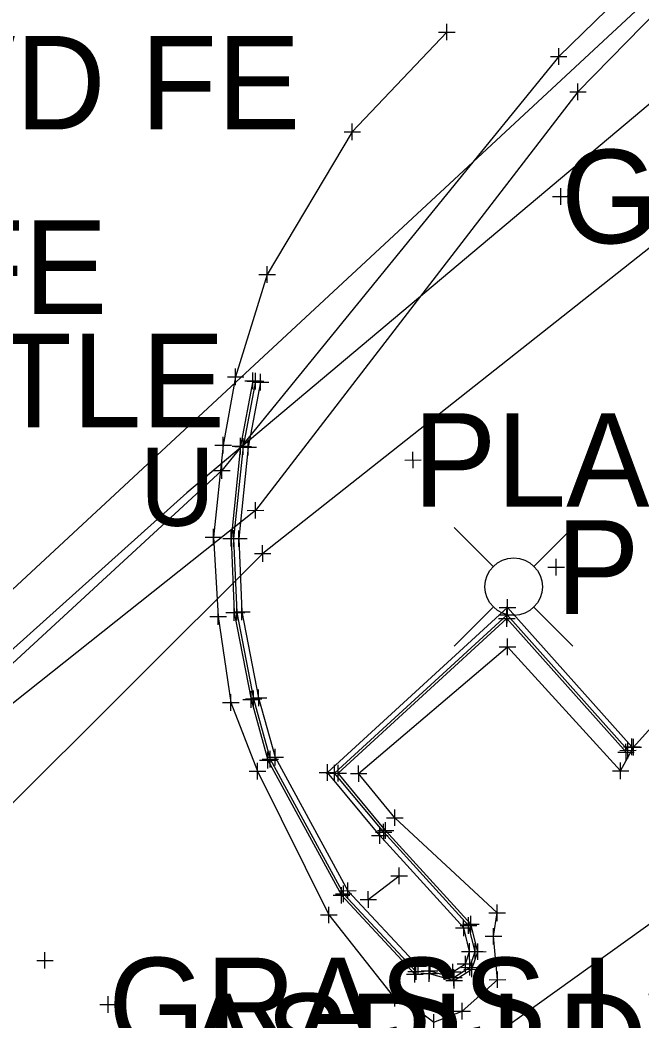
# Model space of a CAD drawing. Extents: x -1 to 1157254, y -1 to 2021979.
# Drawn here: x 1147532.2 to 1147580, y 2017383.4 to 2017460.4 of the extents above; entities that cross this region are included whole.
import ezdxf

# ---------------------------------------------------------------- set-up
doc = ezdxf.new("R2010")
doc.units = 0
for name, color, linetype in [('S_BUILDING_ANNOT', 7, 'Continuous'), ('S_CAL_CORNER_ANNOT', 7, 'Continuous'), ('S_CATCH_BASIN', 7, 'Continuous'), ('S_CONTOUR_MAJOR', 7, 'Continuous'), ('S_CTL_TABLE', 7, 'Continuous'), ('S_DRIVEWAY_ANNOT', 7, 'Continuous'), ('S_DROP_INLET', 7, 'Continuous'), ('S_DTM_PAVEMENT', 7, 'Continuous'), ('S_EDGE_BITUMINOUS_ANNOT', 7, 'Continuous'), ('S_EDGE_PAVEMENT', 7, 'Continuous'), ('S_EDGE_PAVEMENT_ANNOT', 7, 'Continuous'), ('S_ENV_CONSTRAINT', 7, 'Continuous'), ('S_FENCE', 7, 'Continuous'), ('S_GATE', 7, 'Continuous'), ('S_GATE_ANNOT', 7, 'Continuous')]:
    doc.layers.add(name, color=color, linetype=linetype)

msp = doc.modelspace()

# ---------------------------------------------------------------- linework, layer by layer
at = {"layer": 'S_BUILDING_ANNOT'}
for p, q in [((1147565.012, 2017458.822), (1147565.009, 2017460.094)), ((1147564.374, 2017459.456), (1147565.647, 2017459.459)), ((1147565.011, 2017459.458), (1147565.011, 2017459.458)), ((1147573.624, 2017456.932), (1147573.622, 2017458.204)), ((1147572.987, 2017457.566), (1147574.259, 2017457.569)), ((1147573.623, 2017457.568), (1147573.623, 2017457.568)), ((1147575.105, 2017454.225), (1147575.103, 2017455.498)), ((1147574.468, 2017454.86), (1147575.74, 2017454.863)), ((1147575.104, 2017454.862), (1147575.104, 2017454.862)), ((1147557.746, 2017451.147), (1147557.743, 2017452.42)), ((1147557.108, 2017451.782), (1147558.381, 2017451.785)), ((1147557.744, 2017451.783), (1147557.744, 2017451.783)), ((1147573.787, 2017446.169), (1147573.785, 2017447.442)), ((1147573.15, 2017446.804), (1147574.422, 2017446.807)), ((1147573.786, 2017446.805), (1147573.786, 2017446.805)), ((1147551.193, 2017440.159), (1147551.191, 2017441.431)), ((1147550.556, 2017440.794), (1147551.828, 2017440.796)), ((1147551.192, 2017440.795), (1147551.192, 2017440.795)), ((1147548.774, 2017432.29), (1147548.772, 2017433.562)), ((1147548.137, 2017432.924), (1147549.409, 2017432.927)), ((1147548.773, 2017432.926), (1147548.773, 2017432.926)), ((1147549.663, 2017432.585), (1147550.935, 2017432.588)), ((1147550.3, 2017431.951), (1147550.298, 2017433.223)), ((1147550.299, 2017432.587), (1147550.299, 2017432.587)), ((1147550.693, 2017431.877), (1147550.691, 2017433.149)), ((1147550.056, 2017432.511), (1147551.328, 2017432.514)), ((1147550.692, 2017432.513), (1147550.692, 2017432.513)), ((1147547.814, 2017427.03), (1147547.812, 2017428.303)), ((1147549.351, 2017426.933), (1147549.349, 2017428.206)), ((1147549.747, 2017426.875), (1147549.745, 2017428.148)), ((1147547.177, 2017427.665), (1147548.449, 2017427.668)), ((1147547.813, 2017427.667), (1147547.813, 2017427.667)), ((1147548.714, 2017427.568), (1147549.986, 2017427.571)), ((1147549.11, 2017427.51), (1147550.382, 2017427.513)), ((1147549.35, 2017427.57), (1147549.35, 2017427.57)), ((1147549.746, 2017427.512), (1147549.746, 2017427.512)), ((1147561.779, 2017426.526), (1147563.052, 2017426.529)), ((1147562.417, 2017425.891), (1147562.414, 2017427.164)), ((1147562.415, 2017426.528), (1147562.415, 2017426.528)), ((1147547.075, 2017425.716), (1147548.347, 2017425.719)), ((1147547.712, 2017425.081), (1147547.71, 2017426.354)), ((1147547.711, 2017425.718), (1147547.711, 2017425.718)), ((1147549.66, 2017422.652), (1147550.932, 2017422.655)), ((1147550.297, 2017422.017), (1147550.295, 2017423.29)), ((1147550.296, 2017422.653), (1147550.296, 2017422.653)), ((1147547.077, 2017419.959), (1147547.075, 2017421.232)), ((1147548.621, 2017419.854), (1147548.619, 2017421.127)), ((1147549.022, 2017419.842), (1147549.02, 2017421.115)), ((1147546.44, 2017420.594), (1147547.712, 2017420.597)), ((1147547.076, 2017420.595), (1147547.076, 2017420.595)), ((1147547.984, 2017420.489), (1147549.256, 2017420.492)), ((1147548.385, 2017420.477), (1147549.657, 2017420.48)), ((1147548.62, 2017420.49), (1147548.62, 2017420.49)), ((1147549.021, 2017420.478), (1147549.021, 2017420.478)), ((1147550.852, 2017418.691), (1147550.85, 2017419.964)), ((1147550.215, 2017419.326), (1147551.487, 2017419.329)), ((1147550.851, 2017419.327), (1147550.851, 2017419.327)), ((1147573.419, 2017417.651), (1147573.417, 2017418.924)), ((1147572.782, 2017418.286), (1147574.054, 2017418.289)), ((1147573.418, 2017418.287), (1147573.418, 2017418.287)), ((1147569.678, 2017414.552), (1147569.675, 2017415.824)), ((1147547.437, 2017413.844), (1147547.435, 2017415.116)), ((1147548.857, 2017414.169), (1147548.855, 2017415.441)), ((1147549.255, 2017414.216), (1147549.253, 2017415.488)), ((1147569.041, 2017415.187), (1147570.313, 2017415.19)), ((1147569.649, 2017413.983), (1147569.646, 2017415.255)), ((1147569.677, 2017415.188), (1147569.677, 2017415.188)), ((1147546.8, 2017414.479), (1147548.072, 2017414.481)), ((1147547.436, 2017414.48), (1147547.436, 2017414.48)), ((1147548.22, 2017414.804), (1147549.492, 2017414.806)), ((1147548.618, 2017414.851), (1147549.89, 2017414.853)), ((1147548.856, 2017414.805), (1147548.856, 2017414.805)), ((1147549.254, 2017414.852), (1147549.254, 2017414.852)), ((1147569.012, 2017414.618), (1147570.284, 2017414.62)), ((1147569.648, 2017414.619), (1147569.648, 2017414.619)), ((1147569.685, 2017411.513), (1147569.682, 2017412.785)), ((1147569.048, 2017412.148), (1147570.32, 2017412.15)), ((1147569.684, 2017412.149), (1147569.684, 2017412.149)), ((1147550.155, 2017407.507), (1147550.153, 2017408.779)), ((1147550.544, 2017407.599), (1147550.542, 2017408.871)), ((1147548.398, 2017407.233), (1147548.396, 2017408.505)), ((1147549.518, 2017408.142), (1147550.79, 2017408.144)), ((1147549.907, 2017408.234), (1147551.179, 2017408.236)), ((1147550.154, 2017408.143), (1147550.154, 2017408.143)), ((1147550.543, 2017408.235), (1147550.543, 2017408.235)), ((1147547.761, 2017407.868), (1147549.033, 2017407.87)), ((1147548.397, 2017407.869), (1147548.397, 2017407.869)), ((1147579.247, 2017403.819), (1147579.245, 2017405.091)), ((1147579.367, 2017403.799), (1147579.365, 2017405.071)), ((1147551.437, 2017402.869), (1147551.435, 2017404.142)), ((1147551.811, 2017403.02), (1147551.809, 2017404.293)), ((1147578.311, 2017404.187), (1147579.583, 2017404.19)), ((1147578.61, 2017404.453), (1147579.882, 2017404.456)), ((1147578.73, 2017404.433), (1147580.002, 2017404.436)), ((1147578.948, 2017403.552), (1147578.946, 2017404.825)), ((1147578.947, 2017404.189), (1147578.947, 2017404.189)), ((1147579.246, 2017404.455), (1147579.246, 2017404.455)), ((1147579.366, 2017404.435), (1147579.366, 2017404.435)), ((1147550.8, 2017403.504), (1147552.072, 2017403.507)), ((1147551.174, 2017403.655), (1147552.446, 2017403.658)), ((1147551.436, 2017403.506), (1147551.436, 2017403.506)), ((1147551.81, 2017403.657), (1147551.81, 2017403.657)), ((1147549.813, 2017402.583), (1147551.085, 2017402.586)), ((1147550.45, 2017401.948), (1147550.448, 2017403.221)), ((1147550.449, 2017402.585), (1147550.449, 2017402.585)), ((1147555.83, 2017401.844), (1147555.827, 2017403.117)), ((1147556.381, 2017401.806), (1147556.378, 2017403.079)), ((1147558.235, 2017401.758), (1147558.232, 2017403.031)), ((1147577.747, 2017402.609), (1147579.019, 2017402.612)), ((1147578.384, 2017401.974), (1147578.382, 2017403.247)), ((1147578.383, 2017402.611), (1147578.383, 2017402.611)), ((1147555.192, 2017402.479), (1147556.465, 2017402.482)), ((1147555.743, 2017402.441), (1147557.016, 2017402.444)), ((1147555.828, 2017402.481), (1147555.828, 2017402.481)), ((1147556.379, 2017402.443), (1147556.379, 2017402.443)), ((1147557.597, 2017402.393), (1147558.87, 2017402.396)), ((1147558.233, 2017402.395), (1147558.233, 2017402.395)), ((1147561.011, 2017398.366), (1147561.008, 2017399.639)), ((1147560.373, 2017399.001), (1147561.646, 2017399.004)), ((1147561.009, 2017399.002), (1147561.009, 2017399.002)), ((1147559.858, 2017396.987), (1147559.855, 2017398.26)), ((1147560.16, 2017397.25), (1147560.157, 2017398.523)), ((1147559.22, 2017397.622), (1147560.493, 2017397.625)), ((1147559.522, 2017397.885), (1147560.795, 2017397.888)), ((1147559.856, 2017397.623), (1147559.856, 2017397.623)), ((1147560.158, 2017397.886), (1147560.158, 2017397.886)), ((1147561.355, 2017393.89), (1147561.352, 2017395.163)), ((1147560.717, 2017394.525), (1147561.99, 2017394.528)), ((1147561.353, 2017394.526), (1147561.353, 2017394.526)), ((1147556.768, 2017393.387), (1147558.041, 2017393.39)), ((1147557.079, 2017392.516), (1147557.076, 2017393.789)), ((1147557.406, 2017392.752), (1147557.403, 2017394.025)), ((1147557.404, 2017393.388), (1147557.404, 2017393.388)), ((1147558.979, 2017392.081), (1147558.976, 2017393.354)), ((1147556.441, 2017393.151), (1147557.714, 2017393.154)), ((1147557.077, 2017393.152), (1147557.077, 2017393.152)), ((1147558.341, 2017392.716), (1147559.614, 2017392.719)), ((1147558.977, 2017392.717), (1147558.977, 2017392.717)), ((1147555.934, 2017390.884), (1147555.931, 2017392.157)), ((1147568.887, 2017391.043), (1147568.884, 2017392.316)), ((1147555.296, 2017391.519), (1147556.569, 2017391.522)), ((1147555.932, 2017391.52), (1147555.932, 2017391.52)), ((1147566.313, 2017389.886), (1147566.31, 2017391.158)), ((1147566.676, 2017390.081), (1147566.673, 2017391.353)), ((1147568.249, 2017391.678), (1147569.522, 2017391.681)), ((1147568.886, 2017391.679), (1147568.886, 2017391.679)), ((1147565.675, 2017390.521), (1147566.948, 2017390.524)), ((1147566.038, 2017390.716), (1147567.311, 2017390.719)), ((1147566.312, 2017390.522), (1147566.312, 2017390.522)), ((1147566.675, 2017390.717), (1147566.675, 2017390.717)), ((1147568.612, 2017389.244), (1147568.609, 2017390.516)), ((1147567.974, 2017389.879), (1147569.247, 2017389.882)), ((1147568.611, 2017389.88), (1147568.611, 2017389.88)), ((1147566.132, 2017388.716), (1147567.405, 2017388.719)), ((1147566.549, 2017388.701), (1147567.822, 2017388.704)), ((1147566.77, 2017388.081), (1147566.767, 2017389.353)), ((1147566.769, 2017388.717), (1147566.769, 2017388.717)), ((1147567.187, 2017388.066), (1147567.184, 2017389.338)), ((1147567.186, 2017388.702), (1147567.186, 2017388.702)), ((1147533.47, 2017388.027), (1147534.743, 2017388.029)), ((1147534.108, 2017387.392), (1147534.105, 2017388.664)), ((1147534.106, 2017388.028), (1147534.106, 2017388.028)), ((1147562.812, 2017386.947), (1147562.809, 2017388.219)), ((1147563.732, 2017386.988), (1147563.729, 2017388.26)), ((1147566.448, 2017387.115), (1147566.445, 2017388.387)), ((1147566.783, 2017386.855), (1147566.78, 2017388.127)), ((1147562.007, 2017387.175), (1147563.28, 2017387.177)), ((1147562.174, 2017387.582), (1147563.447, 2017387.584)), ((1147562.645, 2017386.54), (1147562.642, 2017387.812)), ((1147562.644, 2017387.176), (1147562.644, 2017387.176)), ((1147562.81, 2017387.583), (1147562.81, 2017387.583)), ((1147563.048, 2017387.221), (1147564.321, 2017387.223)), ((1147563.094, 2017387.623), (1147564.367, 2017387.625)), ((1147563.686, 2017386.586), (1147563.683, 2017387.858)), ((1147563.684, 2017387.222), (1147563.684, 2017387.222)), ((1147563.73, 2017387.624), (1147563.73, 2017387.624)), ((1147565.491, 2017386.5), (1147565.488, 2017387.772)), ((1147565.557, 2017386.067), (1147565.554, 2017387.339)), ((1147565.81, 2017387.75), (1147567.083, 2017387.752)), ((1147566.145, 2017387.49), (1147567.418, 2017387.492)), ((1147566.447, 2017387.751), (1147566.447, 2017387.751)), ((1147566.782, 2017387.491), (1147566.782, 2017387.491)), ((1147568.918, 2017385.905), (1147568.915, 2017387.177)), ((1147564.853, 2017387.135), (1147566.126, 2017387.137)), ((1147564.919, 2017386.702), (1147566.192, 2017386.704)), ((1147565.49, 2017387.136), (1147565.49, 2017387.136)), ((1147565.556, 2017386.703), (1147565.556, 2017386.703)), ((1147568.28, 2017386.54), (1147569.553, 2017386.542)), ((1147568.917, 2017386.541), (1147568.917, 2017386.541)), ((1147561.016, 2017384.468), (1147561.013, 2017385.74)), ((1147561.206, 2017384.796), (1147561.203, 2017386.068)), ((1147538.964, 2017383.993), (1147538.961, 2017385.265)), ((1147560.378, 2017385.103), (1147561.651, 2017385.105)), ((1147560.568, 2017385.431), (1147561.841, 2017385.433)), ((1147561.014, 2017385.104), (1147561.014, 2017385.104)), ((1147561.204, 2017385.432), (1147561.204, 2017385.432)), ((1147538.326, 2017384.628), (1147539.599, 2017384.63)), ((1147538.963, 2017384.629), (1147538.963, 2017384.629)), ((1147565.561, 2017384.123), (1147566.834, 2017384.125)), ((1147566.199, 2017383.488), (1147566.196, 2017384.76)), ((1147566.198, 2017384.124), (1147566.198, 2017384.124)), ((1147564.02, 2017382.624), (1147564.017, 2017383.896))]:
    msp.add_line(p, q, dxfattribs=at)
at = {"layer": 'S_CAL_CORNER_ANNOT'}
msp.add_lwpolyline([(1148176.106, 2017926.044), (1148136.135, 2017895.283), (1148103.217, 2017868.951), (1148054.86, 2017832.593), (1147994.132, 2017784.964), (1147955.313, 2017755.813), (1147823.063, 2017654.265), (1147729.592, 2017581.352), (1147643.019, 2017515.607), (1147594.541, 2017475.046), (1147501.206, 2017388.346), (1147435.286, 2017328.794), (1147395.528, 2017293.456), (1147348.748, 2017254.127), (1147258.659, 2017171.573), (1147166.985, 2017089.787), (1147151.244, 2017076.13), (1147027.412, 2016982.557), (1146975.56, 2016939.412), (1146851.179, 2016835.149), (1146821.227, 2016867.045), (1146788.362, 2016903.205)], dxfattribs=at)
at = {"layer": 'S_CATCH_BASIN'}
for p, q in [((1147568.561, 2017418.361), (1147565.579, 2017421.344)), ((1147571.738, 2017418.361), (1147574.72, 2017421.344)), ((1147568.561, 2017415.185), (1147565.579, 2017412.202)), ((1147571.738, 2017415.185), (1147574.72, 2017412.202))]:
    msp.add_line(p, q, dxfattribs=at)
msp.add_circle((1147570.158, 2017416.781), 2.207, dxfattribs=at)
at = {"layer": 'S_CTL_TABLE'}
for p, q in [((1147549.467, 2017432.622), (1147550.739, 2017432.625)), ((1147550.104, 2017431.988), (1147550.102, 2017433.26)), ((1147550.103, 2017432.624), (1147550.103, 2017432.624)), ((1147549.153, 2017426.962), (1147549.151, 2017428.235)), ((1147548.516, 2017427.597), (1147549.788, 2017427.6)), ((1147549.152, 2017427.599), (1147549.152, 2017427.599)), ((1147548.42, 2017419.86), (1147548.418, 2017421.133)), ((1147547.783, 2017420.495), (1147549.055, 2017420.498)), ((1147548.419, 2017420.496), (1147548.419, 2017420.496)), ((1147548.658, 2017414.146), (1147548.656, 2017415.418)), ((1147569.635, 2017413.699), (1147569.632, 2017414.971)), ((1147548.021, 2017414.781), (1147549.293, 2017414.783)), ((1147548.657, 2017414.782), (1147548.657, 2017414.782)), ((1147568.998, 2017414.334), (1147570.27, 2017414.336)), ((1147569.634, 2017414.335), (1147569.634, 2017414.335)), ((1147549.96, 2017407.461), (1147549.958, 2017408.733)), ((1147549.323, 2017408.096), (1147550.595, 2017408.098)), ((1147549.959, 2017408.097), (1147549.959, 2017408.097)), ((1147578.799, 2017403.419), (1147578.797, 2017404.692)), ((1147550.614, 2017403.429), (1147551.886, 2017403.432)), ((1147551.251, 2017402.794), (1147551.249, 2017404.067)), ((1147551.25, 2017403.431), (1147551.25, 2017403.431)), ((1147578.162, 2017404.054), (1147579.434, 2017404.057)), ((1147578.798, 2017404.056), (1147578.798, 2017404.056)), ((1147556.656, 2017401.788), (1147556.653, 2017403.061)), ((1147556.018, 2017402.423), (1147557.291, 2017402.426)), ((1147556.654, 2017402.425), (1147556.654, 2017402.425)), ((1147559.673, 2017398.016), (1147560.946, 2017398.019)), ((1147560.311, 2017397.381), (1147560.308, 2017398.654)), ((1147560.309, 2017398.017), (1147560.309, 2017398.017)), ((1147556.915, 2017392.398), (1147556.912, 2017393.671)), ((1147556.277, 2017393.033), (1147557.55, 2017393.036)), ((1147556.913, 2017393.034), (1147556.913, 2017393.034)), ((1147566.858, 2017390.178), (1147566.855, 2017391.45)), ((1147566.22, 2017390.813), (1147567.493, 2017390.816)), ((1147566.857, 2017390.814), (1147566.857, 2017390.814)), ((1147567.395, 2017388.058), (1147567.392, 2017389.33)), ((1147566.757, 2017388.693), (1147568.03, 2017388.696)), ((1147566.951, 2017386.725), (1147566.948, 2017387.997)), ((1147567.394, 2017388.694), (1147567.394, 2017388.694)), ((1147562.562, 2017386.336), (1147562.559, 2017387.608)), ((1147563.663, 2017386.385), (1147563.66, 2017387.657)), ((1147566.313, 2017387.36), (1147567.586, 2017387.362)), ((1147566.95, 2017387.361), (1147566.95, 2017387.361)), ((1147561.924, 2017386.971), (1147563.197, 2017386.973)), ((1147562.56, 2017386.972), (1147562.56, 2017386.972)), ((1147563.025, 2017387.02), (1147564.298, 2017387.022)), ((1147563.661, 2017387.021), (1147563.661, 2017387.021)), ((1147564.952, 2017386.485), (1147566.225, 2017386.487)), ((1147565.59, 2017385.85), (1147565.587, 2017387.122)), ((1147565.589, 2017386.486), (1147565.589, 2017386.486))]:
    msp.add_line(p, q, dxfattribs=at)
at = {"layer": 'S_DRIVEWAY_ANNOT'}
for points in [[(1147744.553, 2017594.497), (1147743.321, 2017593.742), (1147727.496, 2017582.827), (1147686.458, 2017550.47), (1147642.4, 2017515.309), (1147602.356, 2017485.525), (1147573.623, 2017457.568), (1147547.711, 2017425.718), (1147524.365, 2017404.198), (1147507.721, 2017393.364), (1147500.705, 2017387.535)], [(1147745.212, 2017593.731), (1147744.124, 2017592.133), (1147729.537, 2017581.38), (1147687.377, 2017548.909), (1147643.197, 2017513.751), (1147603.766, 2017484.135), (1147575.104, 2017454.862), (1147550.296, 2017422.653), (1147525.798, 2017403.162), (1147509.598, 2017391.633), (1147502.188, 2017385.525)]]:
    msp.add_lwpolyline(points, dxfattribs=at)
at = {"layer": 'S_DROP_INLET'}
msp.add_lwpolyline([(1148195.528, 2017935.768), (1148138.819, 2017892.989), (1148034.426, 2017809.592), (1147909.475, 2017714.316), (1147828.883, 2017654.708), (1147681.29, 2017538.62), (1147545.027, 2017424.01), (1147436.651, 2017326.836), (1147356.287, 2017257.736), (1147237.669, 2017148.836), (1147152.37, 2017082.268), (1147079.411, 2017020.236), (1146950.459, 2016911.581), (1146849.377, 2016826.65), (1146763.176, 2016745.201), (1146663.113, 2016665.755), (1146626.022, 2016634.68), (1146520.536, 2016557.464), (1146484.38, 2016531.034)], dxfattribs=at)
at = {"layer": 'S_DTM_PAVEMENT'}
msp.add_lwpolyline([(1147558.977, 2017392.717), (1147561.353, 2017394.526)], dxfattribs=at)
at = {"layer": 'S_EDGE_BITUMINOUS_ANNOT'}
for points in [[(1147550.103, 2017432.624), (1147549.152, 2017427.599), (1147548.419, 2017420.496), (1147548.657, 2017414.782), (1147549.959, 2017408.097), (1147551.25, 2017403.431), (1147556.913, 2017393.034), (1147562.56, 2017386.972), (1147563.661, 2017387.021), (1147565.589, 2017386.486), (1147566.95, 2017387.361), (1147567.394, 2017388.694), (1147566.857, 2017390.814), (1147560.309, 2017398.017), (1147556.654, 2017402.425), (1147569.634, 2017414.335), (1147578.798, 2017404.056)], [(1147592.174, 2017399.091), (1147569.436, 2017382.781), (1147536.223, 2017355.764), (1147514.112, 2017335.991), (1147488.882, 2017309.123), (1147476.222, 2017295.791)]]:
    msp.add_lwpolyline(points, dxfattribs=at)
at = {"layer": 'S_EDGE_PAVEMENT'}
for points in [[(1147550.299, 2017432.587), (1147549.35, 2017427.57), (1147548.62, 2017420.49), (1147548.856, 2017414.805), (1147550.154, 2017408.143), (1147551.436, 2017403.506), (1147557.077, 2017393.152), (1147562.644, 2017387.176), (1147563.684, 2017387.222), (1147565.556, 2017386.703), (1147566.782, 2017387.491), (1147567.186, 2017388.702), (1147566.675, 2017390.717), (1147560.158, 2017397.886), (1147556.379, 2017402.443), (1147569.648, 2017414.619), (1147578.947, 2017404.189)], [(1147550.692, 2017432.513), (1147549.746, 2017427.512), (1147549.021, 2017420.478), (1147549.254, 2017414.852), (1147550.543, 2017408.235), (1147551.81, 2017403.657), (1147557.404, 2017393.388), (1147562.81, 2017387.583), (1147563.73, 2017387.624), (1147565.49, 2017387.136), (1147566.447, 2017387.751), (1147566.769, 2017388.717), (1147566.312, 2017390.522), (1147559.856, 2017397.623), (1147555.828, 2017402.481), (1147569.677, 2017415.188), (1147579.246, 2017404.455)]]:
    msp.add_lwpolyline(points, dxfattribs=at)
at = {"layer": 'S_EDGE_PAVEMENT_ANNOT'}
msp.add_lwpolyline([(1147561.204, 2017385.432), (1147564.019, 2017383.26), (1147566.198, 2017384.124), (1147568.917, 2017386.541), (1147568.611, 2017389.88), (1147568.886, 2017391.679), (1147561.009, 2017399.002), (1147558.233, 2017402.395), (1147569.684, 2017412.149), (1147578.383, 2017402.611), (1147579.366, 2017404.435), (1147581.64, 2017406.951), (1147580.688, 2017428.274), (1147592.173, 2017427.088), (1147592.068, 2017407.647), (1147593.145, 2017391.963), (1147593.778, 2017344.024)], dxfattribs=at)
at = {"layer": 'S_ENV_CONSTRAINT'}
msp.add_lwpolyline([(1147565.011, 2017459.458), (1147557.744, 2017451.783), (1147551.192, 2017440.795), (1147548.773, 2017432.926), (1147547.813, 2017427.667), (1147547.076, 2017420.595), (1147547.436, 2017414.48), (1147548.397, 2017407.869), (1147550.449, 2017402.585), (1147555.932, 2017391.52), (1147561.014, 2017385.104)], dxfattribs=at)
at = {"layer": 'S_FENCE'}
msp.add_lwpolyline([(1148182.052, 2017918.064), (1148146.031, 2017882.736), (1148036.878, 2017800.655), (1147915.132, 2017710.899), (1147841.973, 2017653.39), (1147689.753, 2017529.104), (1147550.851, 2017419.327), (1147452.642, 2017321.351), (1147370.713, 2017243.519), (1147258.326, 2017138.296), (1147166.15, 2017078.021), (1147070.177, 2016992.832), (1146962.813, 2016905.873), (1146854.859, 2016827.911), (1146747.328, 2016742.807), (1146665.816, 2016680.994), (1146623.062, 2016638.597), (1146514.264, 2016556.707), (1146391.385, 2016471.398), (1146322.085, 2016427.508), (1146235.838, 2016373.998), (1146176.662, 2016335.007), (1146181.421, 2016326.5)], dxfattribs=at)

# ---------------------------------------------------------------- texts
at = {"layer": 'S_CONTOUR_MAJOR'}
msp.add_text('U', height=5.998, dxfattribs=at).set_placement((1147541.399, 2017421.466))
at = {"layer": 'S_GATE'}
for s, p in [('2 RAIL WD FE', (1147490.627, 2017451.962)), ('GRASS', (1147573.786, 2017443.205)), ('2 RAIL WD FE', (1147475.786, 2017437.761)), ('PLANTER', (1147562.415, 2017422.928)), ('PLANTIER PLANTER', (1147573.418, 2017414.687)), ('GRASS LOT', (1147538.963, 2017381.029)), ('ASPH DW', (1147544.625, 2017378.27))]:
    msp.add_text(s, height=7.2, dxfattribs=at).set_placement(p)
at = {"layer": 'S_GATE_ANNOT'}
msp.add_text('6" CREPE MYRTLE', height=7.2, dxfattribs=at).set_placement((1147461.608, 2017429.047))

doc.saveas('drawing.dxf')
